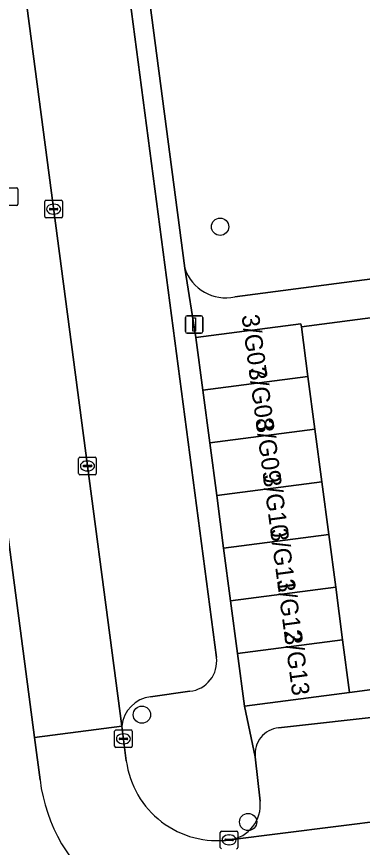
# Model space of a CAD drawing. Extents: x 161084 to 161928, y 385354 to 386522.
# Drawn here: x 161251.95 to 161271.54, y 385622.36 to 385669.53 of the extents above; entities that cross this region are included whole.
import ezdxf

# ---------------------------------------------------------------- set-up
doc = ezdxf.new("R2010")
doc.units = 0
for name, color, linetype in [('IMGEO_Boom', 7, 'Continuous'), ('IMGEO_Groenvoorziening', 7, 'Continuous'), ('IMGEO_Kolk', 7, 'Continuous'), ('IMGEO_Lichtmast', 7, 'Continuous'), ('IMGEO_Muur', 7, 'Continuous'), ('IMGEO_Pand', 7, 'Continuous'), ('IMGEO_Pand_nummerreeks', 7, 'Continuous'), ('IMGEO_Parkeervlak_open', 7, 'Continuous'), ('IMGEO_Rijbaan_lokaal_open', 7, 'Continuous'), ('IMGEO_Rioolput', 7, 'Continuous'), ('IMGEO_Voetpad_open', 7, 'Continuous')]:
    doc.layers.add(name, color=color, linetype=linetype)

msp = doc.modelspace()

# ---------------------------------------------------------------- linework, layer by layer
at = {"layer": 'IMGEO_Boom'}
for centre in [(161263.477, 385657.598), (161259.044, 385629.893), (161265.066, 385623.803)]:
    msp.add_circle(centre, 0.489, dxfattribs=at)
at = {"layer": 'IMGEO_Groenvoorziening'}
for points in [[(161257.376, 385686.442), (161261.478, 385655.239)], [(161264.31, 385653.617), (161285.207, 385656.371)]]:
    msp.add_lwpolyline(points, dxfattribs=at)
msp.add_arc((161263.796, 385656.002), 2.44, 198.2318, 282.1652, dxfattribs=at)
at = {"layer": 'IMGEO_Kolk'}
for p, q in [((161253.543, 385658.172), (161253.543, 385659.024)), ((161253.618, 385659.098), (161254.47, 385659.098)), ((161254.544, 385659.024), (161254.544, 385658.172)), ((161253.802, 385658.592), (161253.802, 385658.604)), ((161254.24, 385658.555), (161253.842, 385658.555)), ((161253.845, 385658.641), (161254.243, 385658.641)), ((161254.031, 385658.878), (161254.056, 385658.878)), ((161254.286, 385658.604), (161254.286, 385658.592)), ((161254.47, 385658.098), (161253.618, 385658.098)), ((161254.054, 385658.318), (161254.029, 385658.318)), ((161255.46, 385643.592), (161255.46, 385644.444)), ((161255.535, 385644.518), (161256.387, 385644.518)), ((161255.948, 385644.298), (161255.973, 385644.298)), ((161256.461, 385644.444), (161256.461, 385643.592)), ((161255.719, 385644.012), (161255.719, 385644.024)), ((161256.157, 385643.975), (161255.759, 385643.975)), ((161255.762, 385644.061), (161256.16, 385644.061)), ((161256.203, 385644.024), (161256.203, 385644.012)), ((161256.387, 385643.518), (161255.535, 385643.518)), ((161255.971, 385643.738), (161255.946, 385643.738)), ((161257.497, 385628.1), (161257.497, 385628.952)), ((161257.572, 385629.026), (161258.424, 385629.026)), ((161257.985, 385628.806), (161258.01, 385628.806)), ((161258.498, 385628.952), (161258.498, 385628.1)), ((161257.756, 385628.52), (161257.756, 385628.532)), ((161258.194, 385628.483), (161257.796, 385628.483)), ((161257.799, 385628.569), (161258.197, 385628.569)), ((161258.24, 385628.532), (161258.24, 385628.52)), ((161258.424, 385628.026), (161257.572, 385628.026)), ((161258.008, 385628.246), (161257.983, 385628.246)), ((161263.487, 385622.36), (161263.487, 385623.212)), ((161263.562, 385623.286), (161264.414, 385623.286)), ((161263.975, 385623.066), (161264, 385623.066)), ((161264.488, 385623.212), (161264.488, 385622.36)), ((161263.746, 385622.78), (161263.746, 385622.792)), ((161264.184, 385622.743), (161263.786, 385622.743)), ((161263.789, 385622.829), (161264.187, 385622.829)), ((161264.23, 385622.792), (161264.23, 385622.78)), ((161263.998, 385622.506), (161263.973, 385622.506))]:
    msp.add_line(p, q, dxfattribs=at)
for points in [[(161253.543, 385658.172), (161253.543, 385659.024)], [(161253.618, 385659.098), (161254.47, 385659.098)], [(161254.544, 385659.024), (161254.544, 385658.172)], [(161254.47, 385658.098), (161253.618, 385658.098)], [(161255.46, 385643.592), (161255.46, 385644.444)], [(161255.535, 385644.518), (161256.387, 385644.518)], [(161256.461, 385644.444), (161256.461, 385643.592)], [(161256.387, 385643.518), (161255.535, 385643.518)], [(161257.497, 385628.1), (161257.497, 385628.952)], [(161257.572, 385629.026), (161258.424, 385629.026)], [(161258.498, 385628.952), (161258.498, 385628.1)], [(161258.424, 385628.026), (161257.572, 385628.026)], [(161263.487, 385622.36), (161263.487, 385623.212)], [(161263.562, 385623.286), (161264.414, 385623.286)], [(161264.488, 385623.212), (161264.488, 385622.36)]]:
    msp.add_lwpolyline(points, dxfattribs=at)
for centre, radius, start, end in [((161253.62, 385659.022), 0.0765, 91.552, 178.448), ((161253.62, 385659.022), 0.0765, 91.552, 178.448), ((161254.468, 385659.022), 0.0765, 1.552, 88.448), ((161254.468, 385659.022), 0.0765, 1.552, 88.448), ((161253.842, 385658.601), 0.0403, 85.8775, 175.7526), ((161253.839, 385658.591), 0.0366, 178.938, 274.7102), ((161254.243, 385658.598), 0.043, 264.8664, 352.4533), ((161254.247, 385658.603), 0.0386, 1.7309, 96.639), ((161253.62, 385658.174), 0.0765, 181.552, 268.448), ((161253.62, 385658.174), 0.0765, 181.552, 268.448), ((161254.468, 385658.174), 0.0765, 271.552, 358.448), ((161254.468, 385658.174), 0.0765, 271.552, 358.448), ((161255.537, 385644.442), 0.0765, 91.552, 178.448), ((161255.537, 385644.442), 0.0765, 91.552, 178.448), ((161256.385, 385644.442), 0.0765, 1.552, 88.448), ((161256.385, 385644.442), 0.0765, 1.552, 88.448), ((161255.759, 385644.021), 0.0403, 85.8775, 175.7526), ((161255.756, 385644.011), 0.0366, 178.938, 274.7102), ((161256.16, 385644.018), 0.043, 264.8664, 352.4533), ((161256.164, 385644.023), 0.0386, 1.7309, 96.639), ((161255.537, 385643.594), 0.0765, 181.552, 268.448), ((161255.537, 385643.594), 0.0765, 181.552, 268.448), ((161256.385, 385643.594), 0.0765, 271.552, 358.448), ((161256.385, 385643.594), 0.0765, 271.552, 358.448), ((161257.574, 385628.95), 0.0765, 91.552, 178.448), ((161257.574, 385628.95), 0.0765, 91.552, 178.448), ((161258.422, 385628.95), 0.0765, 1.552, 88.448), ((161258.422, 385628.95), 0.0765, 1.552, 88.448), ((161257.796, 385628.529), 0.0403, 85.8775, 175.7526), ((161257.793, 385628.519), 0.0366, 178.938, 274.7102), ((161258.197, 385628.526), 0.043, 264.8664, 352.4533), ((161258.201, 385628.531), 0.0386, 1.7309, 96.639), ((161257.574, 385628.102), 0.0765, 181.552, 268.448), ((161257.574, 385628.102), 0.0765, 181.552, 268.448), ((161258.422, 385628.102), 0.0765, 271.552, 358.448), ((161258.422, 385628.102), 0.0765, 271.552, 358.448), ((161263.564, 385623.21), 0.0765, 91.552, 178.448), ((161263.564, 385623.21), 0.0765, 91.552, 178.448), ((161264.412, 385623.21), 0.0765, 1.552, 88.448), ((161264.412, 385623.21), 0.0765, 1.552, 88.448), ((161263.786, 385622.789), 0.0403, 85.8775, 175.7526), ((161263.783, 385622.779), 0.0366, 178.938, 274.7102), ((161264.187, 385622.786), 0.043, 264.8664, 352.4533), ((161264.191, 385622.791), 0.0386, 1.7309, 96.639), ((161263.564, 385622.362), 0.0765, 181.552, 268.448), ((161263.564, 385622.362), 0.0765, 181.552, 268.448), ((161264.412, 385622.362), 0.0765, 271.552, 358.448), ((161264.412, 385622.362), 0.0765, 271.552, 358.448)]:
    msp.add_arc(centre, radius, start, end, dxfattribs=at)
for centre, major_axis, ratio, start_param, end_param in [((161254.03, 385658.598), (-0.387, 0.002), 0.722429, 4.712389, 7.853982), ((161254.055, 385658.598), (-0.39, 0.002), 0.717154, 1.570796, 4.712389), ((161255.947, 385644.018), (-0.387, 0.002), 0.722429, 4.712389, 7.853982), ((161255.972, 385644.018), (-0.39, 0.002), 0.717154, 1.570796, 4.712389), ((161257.984, 385628.526), (-0.387, 0.002), 0.722429, 4.712389, 7.853982), ((161258.009, 385628.526), (-0.39, 0.002), 0.717154, 1.570796, 4.712389), ((161263.974, 385622.786), (-0.387, 0.002), 0.722429, 4.712389, 7.853982), ((161263.999, 385622.786), (-0.39, 0.002), 0.717154, 1.570796, 4.712389)]:
    msp.add_ellipse(centre, major_axis=major_axis, ratio=ratio, start_param=start_param, end_param=end_param, dxfattribs=at)
at = {"layer": 'IMGEO_Lichtmast'}
for p, q in [((161261.508, 385651.648), (161261.508, 385652.448)), ((161261.508, 385652.448), (161261.508, 385651.648)), ((161261.608, 385652.548), (161262.398, 385652.548)), ((161262.398, 385652.548), (161261.608, 385652.548)), ((161262.498, 385652.448), (161262.498, 385651.648)), ((161262.498, 385651.648), (161262.498, 385652.448)), ((161262.398, 385651.548), (161261.608, 385651.548)), ((161261.608, 385651.548), (161262.398, 385651.548))]:
    msp.add_line(p, q, dxfattribs=at)
msp.add_lwpolyline([(161261.928, 385652.423), (161262.078, 385652.423), (161262.078, 385651.673), (161261.928, 385651.673), (161261.928, 385652.423)], dxfattribs=at)
for centre, start, end in [((161261.608, 385652.448), 90, 180), ((161261.608, 385652.448), 90, 180), ((161262.398, 385652.448), 0, 90), ((161262.398, 385652.448), 360, 90), ((161261.608, 385651.648), 180, 270), ((161261.608, 385651.648), 180, 270), ((161262.398, 385651.648), 270, 0), ((161262.398, 385651.648), 270, 0)]:
    msp.add_arc(centre, 0.1, start, end, dxfattribs=at)
at = {"layer": 'IMGEO_Muur'}
msp.add_lwpolyline([(161268.082, 385651.914), (161276.025, 385652.959)], dxfattribs=at)
at = {"layer": 'IMGEO_Pand'}
for points in [[(161262.495, 385648.315), (161268.453, 385649.1), (161268.082, 385651.914), (161268.059, 385652.09), (161262.101, 385651.304)], [(161262.889, 385645.325), (161268.847, 385646.11), (161268.453, 385649.1), (161262.495, 385648.315)], [(161263.283, 385642.336), (161269.241, 385643.121), (161268.847, 385646.11), (161262.889, 385645.325)], [(161263.677, 385639.346), (161269.635, 385640.132), (161269.241, 385643.121), (161263.283, 385642.336)], [(161264.071, 385636.357), (161270.029, 385637.142), (161269.635, 385640.132), (161263.677, 385639.346)], [(161264.465, 385633.367), (161270.423, 385634.153), (161270.029, 385637.142), (161264.071, 385636.357)], [(161270.817, 385631.163), (161270.423, 385634.153), (161264.465, 385633.367), (161264.859, 385630.378)]]:
    msp.add_lwpolyline(points, close=True, dxfattribs=at)
at = {"layer": 'IMGEO_Parkeervlak_open'}
for points in [[(161250.003, 385689.098), (161257.907, 385629.249)], [(161263.269, 385633.137), (161256.381, 385685.659)], [(161259.54, 385630.911), (161261.766, 385631.224)], [(161283.865, 385631.036), (161277.788, 385630.365), (161273.053, 385629.843), (161266.793, 385629.152)], [(161265.467, 385627.498), (161265.742, 385624.989)], [(161264.027, 385622.789), (161288.064, 385625.813)]]:
    msp.add_lwpolyline(points, dxfattribs=at)
for centre, radius, start, end in [((161261.583, 385632.915), 1.701, 276.1878, 7.5004), ((161259.755, 385629.066), 1.857, 96.6516, 174.3569), ((161266.955, 385627.663), 1.498, 96.2273, 186.3349), ((161263.753, 385624.771), 2.001, 277.8795, 6.2444)]:
    msp.add_arc(centre, radius, start, end, dxfattribs=at)
at = {"layer": 'IMGEO_Rijbaan_lokaal_open'}
for points in [[(161244.898, 385690.013), (161252.953, 385628.599), (161257.907, 385629.249), (161250.003, 385689.098)], [(161258.162, 385627.271), (161257.907, 385629.249), (161252.953, 385628.599), (161253.269, 385626.19)], [(161288.264, 385625.838), (161288.064, 385625.813), (161264.027, 385622.789)]]:
    msp.add_lwpolyline(points, dxfattribs=at)
msp.add_lwpolyline([(161281.626, 385632.587), (161281.231, 385635.587), (161278.357, 385635.22), (161277.969, 385638.168), (161277.581, 385641.126), (161277.192, 385644.084), (161276.803, 385647.043), (161276.414, 385650.001), (161276.025, 385652.959), (161268.082, 385651.914), (161268.453, 385649.1), (161268.847, 385646.11), (161269.241, 385643.121), (161269.635, 385640.132), (161270.029, 385637.142), (161270.423, 385634.153), (161270.817, 385631.163)], close=True, dxfattribs=at)
for centre, radius, start, end in [((161263.324, 385627.948), 5.207, 187.47, 277.7563), ((161262.983, 385627.462), 9.797, 187.4611, 277.501)]:
    msp.add_arc(centre, radius, start, end, dxfattribs=at)
at = {"layer": 'IMGEO_Rioolput'}
for p, q in [((161251.093, 385659.808), (161251.945, 385659.808)), ((161252.019, 385659.734), (161252.019, 385658.882)), ((161251.945, 385658.808), (161251.093, 385658.808))]:
    msp.add_line(p, q, dxfattribs=at)
for points in [[(161251.093, 385659.808), (161251.945, 385659.808)], [(161252.019, 385659.734), (161252.019, 385658.882)], [(161251.945, 385658.808), (161251.093, 385658.808)]]:
    msp.add_lwpolyline(points, dxfattribs=at)
for centre, start, end in [((161251.943, 385659.732), 1.552, 88.448), ((161251.943, 385659.732), 1.552, 88.448), ((161251.943, 385658.884), 271.552, 358.448), ((161251.943, 385658.884), 271.552, 358.448)]:
    msp.add_arc(centre, 0.0765, start, end, dxfattribs=at)
at = {"layer": 'IMGEO_Voetpad_open'}
for points in [[(161253.269, 385626.19), (161252.953, 385628.599), (161244.898, 385690.013)], [(161265.742, 385624.989), (161265.467, 385627.498), (161264.859, 385630.378), (161264.465, 385633.367), (161264.071, 385636.357), (161263.677, 385639.346), (161263.283, 385642.336), (161262.889, 385645.325), (161262.495, 385648.315), (161262.101, 385651.304), (161261.478, 385655.239), (161257.376, 385686.442)], [(161256.381, 385685.659), (161263.269, 385633.137)], [(161285.207, 385656.371), (161264.31, 385653.617)], [(161261.478, 385655.239), (161262.101, 385651.304), (161268.059, 385652.09), (161268.082, 385651.914), (161276.025, 385652.959), (161282.028, 385653.748), (161285.426, 385654.112)], [(161285.498, 385629.83), (161285.135, 385631.775), (161281.791, 385631.335), (161281.626, 385632.587), (161270.817, 385631.163), (161264.859, 385630.378), (161265.467, 385627.498)], [(161261.766, 385631.224), (161259.54, 385630.911)], [(161266.793, 385629.152), (161273.053, 385629.843), (161272.999, 385630.339), (161277.734, 385630.861)], [(161257.907, 385629.249), (161258.162, 385627.271)]]:
    msp.add_lwpolyline(points, dxfattribs=at)
for centre, radius, start, end in [((161263.796, 385656.002), 2.44, 198.2318, 282.1652), ((161261.583, 385632.915), 1.701, 276.1878, 7.5004), ((161259.755, 385629.066), 1.857, 96.6516, 174.3569), ((161266.955, 385627.663), 1.498, 96.2273, 186.3349), ((161263.324, 385627.948), 5.207, 187.47, 277.7563), ((161262.983, 385627.462), 9.797, 187.4611, 277.501), ((161263.753, 385624.771), 2.001, 277.8795, 6.2444)]:
    msp.add_arc(centre, radius, start, end, dxfattribs=at)

# ---------------------------------------------------------------- texts
at = {"layer": 'IMGEO_Pand_nummerreeks'}
for s, p in [('3/G07', (161264.689, 385652.556)), ('3/G08', (161265.089, 385649.565)), ('3/G09', (161265.488, 385646.584)), ('3/G10', (161265.9, 385643.499)), ('3/G11', (161266.314, 385640.406)), ('3/G12', (161266.698, 385637.533)), ('3/G13', (161267.098, 385634.54))]:
    msp.add_text(s, height=1, rotation=277.616, dxfattribs=at).set_placement(p)

doc.saveas('drawing.dxf')
